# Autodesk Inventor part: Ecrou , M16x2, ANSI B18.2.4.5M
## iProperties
Shininess: 64.0
Length Units: 11269
Angle Units: 11279
Time Units: 11290
Mass Units: 11283
Length Display Precision: 3
Angle Display Precision: 2
Compacted: True
Part Number: Ecrou , M16x2, ANSI B18.2.4.5M
Document SubType Name: Modeling
Created: 2005-02
Material: Par défaut
Designer: LEGERET Philippe
Catalog Web Link: www.traceparts.com
Description: Ecrou bas hexagonal, M16x2, ANSI B18.2.4.5M
Density: 0.0
Volumn: 0.0
Area: 0.0
PropertySet Name: Model Information
Control State: 0
Master: False
Checked Out: False
Author: Trace Parts S.A.
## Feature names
1. Base1
